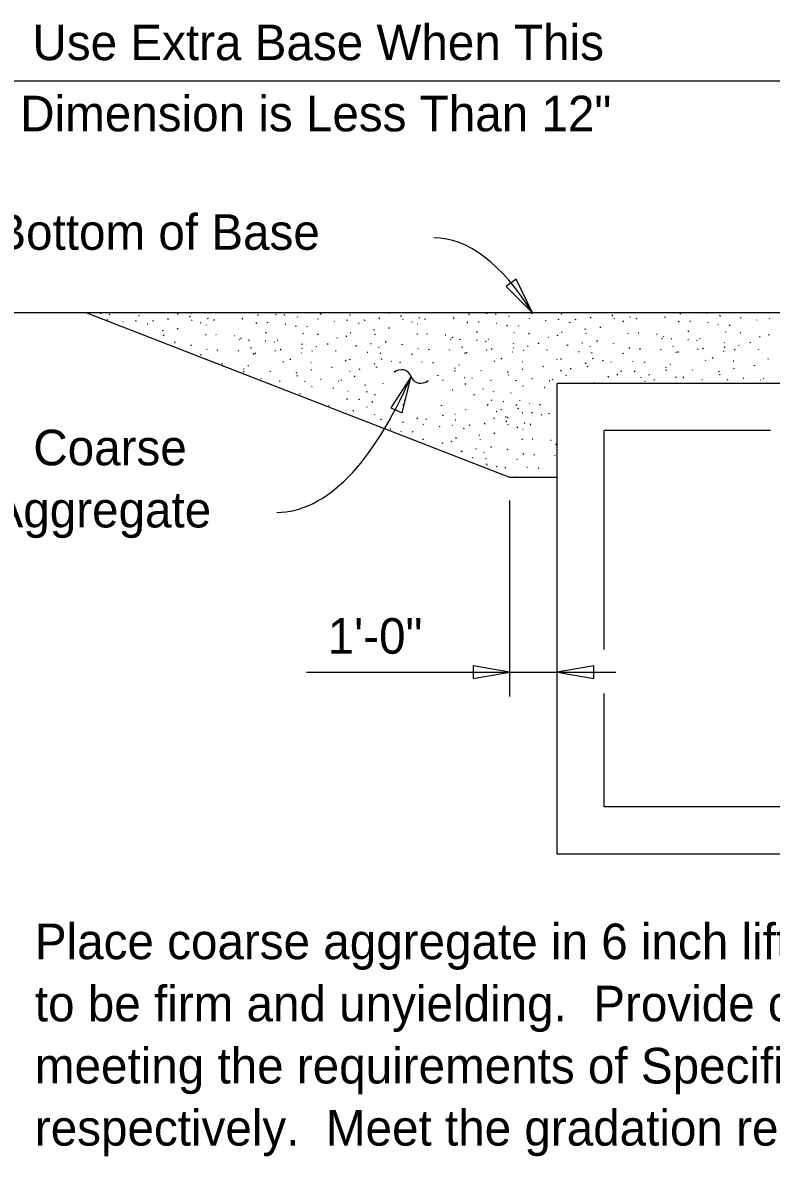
# Model space of a CAD drawing. Extents: x 1.4 to 54.1, y -0.5 to 22.6.
# Drawn here: x 23.827 to 27.007, y 6.775 to 11.592 of the extents above; entities that cross this region are included whole.
import ezdxf

# ---------------------------------------------------------------- set-up
doc = ezdxf.new("R2010")
doc.units = 0
for name, color, linetype in [('AdhocPoint_dp', 7, 'Continuous'), ('Border', 7, 'Continuous'), ('Leader', 7, 'Continuous'), ('PlotBorder_dp', 7, 'Continuous'), ('WallConc', 7, 'Continuous')]:
    doc.layers.add(name, color=color, linetype=linetype)

msp = doc.modelspace()

# ---------------------------------------------------------------- linework, layer by layer
at = {"layer": 'Border'}
for p, q in [((24.1612, 10.3536), (24.1592, 10.3569)), ((24.487, 10.3527), (24.4858, 10.3566)), ((24.5439, 10.3597), (24.5413, 10.3561)), ((25.0583, 10.3566), (25.0564, 10.3597)), ((25.3841, 10.3557), (25.3828, 10.3596)), ((25.4389, 10.3597), (25.4384, 10.359)), ((25.8005, 10.3537), (25.7985, 10.357)), ((25.9553, 10.3596), (25.9552, 10.3597)), ((25.9919, 10.3557), (25.9899, 10.3589)), ((26.2812, 10.3586), (26.2808, 10.3597)), ((26.6976, 10.3567), (26.6956, 10.3597)), ((26.7347, 10.3547), (26.7328, 10.358)), ((26.8889, 10.3586), (26.8883, 10.3597)), ((24.1873, 10.3275), (24.1854, 10.3307)), ((24.1978, 10.3497), (24.1958, 10.353)), ((24.2546, 10.3203), (24.2527, 10.3196)), ((24.3082, 10.3268), (24.3069, 10.3229)), ((24.3232, 10.3471), (24.32, 10.3477)), ((24.3592, 10.3111), (24.356, 10.3117)), ((24.3828, 10.3229), (24.3815, 10.3268)), ((24.4455, 10.3347), (24.4429, 10.3307)), ((24.5381, 10.3449), (24.5355, 10.341)), ((24.5469, 10.3263), (24.545, 10.3296)), ((24.5852, 10.3188), (24.5825, 10.3149)), ((24.6152, 10.3331), (24.6132, 10.3364)), ((24.6415, 10.3265), (24.6395, 10.3311)), ((24.761, 10.3363), (24.7584, 10.3325)), ((24.8198, 10.318), (24.8172, 10.3141)), ((24.8283, 10.3488), (24.8244, 10.3488)), ((24.8688, 10.316), (24.8668, 10.3193)), ((24.9034, 10.3507), (24.9014, 10.354)), ((24.9406, 10.3487), (24.9387, 10.352)), ((24.9446, 10.3096), (24.9426, 10.3128)), ((24.9949, 10.3429), (24.9929, 10.3396)), ((25.0844, 10.3305), (25.0824, 10.3337)), ((25.0948, 10.3527), (25.0929, 10.3559)), ((25.1517, 10.3233), (25.1497, 10.3226)), ((25.2053, 10.3298), (25.2039, 10.3259)), ((25.2203, 10.3501), (25.2171, 10.3507)), ((25.2563, 10.3141), (25.253, 10.3147)), ((25.2798, 10.3258), (25.2786, 10.3298)), ((25.3426, 10.3377), (25.34, 10.3337)), ((25.4352, 10.3479), (25.4326, 10.3439)), ((25.4439, 10.3293), (25.442, 10.3326)), ((25.4822, 10.3218), (25.4796, 10.3179)), ((25.5052, 10.3106), (25.5041, 10.3109)), ((25.5123, 10.3361), (25.5103, 10.3394)), ((25.5385, 10.3295), (25.5365, 10.3341)), ((25.6581, 10.3393), (25.6555, 10.3355)), ((25.7168, 10.321), (25.7142, 10.3171)), ((25.7253, 10.3518), (25.7214, 10.3517)), ((25.7658, 10.319), (25.7638, 10.3223)), ((25.8377, 10.3517), (25.8357, 10.355)), ((25.8416, 10.3125), (25.8396, 10.3158)), ((25.8919, 10.3459), (25.89, 10.3426)), ((25.9815, 10.3335), (25.9795, 10.3367)), ((26.0487, 10.3263), (26.0468, 10.3256)), ((26.1023, 10.3327), (26.101, 10.3289)), ((26.1173, 10.353), (26.1141, 10.3537)), ((26.1533, 10.317), (26.1501, 10.3177)), ((26.1769, 10.3288), (26.1757, 10.3328)), ((26.2396, 10.3406), (26.237, 10.3367)), ((26.3322, 10.3509), (26.3296, 10.3469)), ((26.341, 10.3323), (26.3391, 10.3356)), ((26.3793, 10.3248), (26.3766, 10.3208)), ((26.4023, 10.3136), (26.4011, 10.3139)), ((26.4093, 10.3391), (26.4074, 10.3424)), ((26.4356, 10.3325), (26.4336, 10.3371)), ((26.5551, 10.3423), (26.5525, 10.3384)), ((26.6139, 10.324), (26.6113, 10.3201)), ((26.6224, 10.3548), (26.6185, 10.3547)), ((26.6629, 10.322), (26.6609, 10.3253)), ((26.7387, 10.3155), (26.7367, 10.3188)), ((26.783, 10.3064), (26.7812, 10.3096)), ((26.789, 10.3488), (26.787, 10.3456)), ((26.8785, 10.3365), (26.8765, 10.3397)), ((26.9458, 10.3293), (26.9438, 10.3286)), ((26.9994, 10.3357), (26.998, 10.3319)), ((24.3239, 10.2732), (24.323, 10.2718)), ((24.424, 10.2817), (24.4227, 10.2857)), ((24.4279, 10.2622), (24.426, 10.2654)), ((24.4867, 10.2935), (24.4841, 10.2895)), ((24.6065, 10.2641), (24.6044, 10.2674)), ((24.6082, 10.3076), (24.607, 10.3079)), ((24.6493, 10.2665), (24.6473, 10.2671)), ((24.7276, 10.2612), (24.7251, 10.2613)), ((24.8609, 10.2769), (24.8583, 10.273)), ((24.9889, 10.3004), (24.987, 10.3036)), ((25.0197, 10.2696), (25.0178, 10.2729)), ((25.0197, 10.2696), (25.0178, 10.2729)), ((25.036, 10.3017), (25.0341, 10.2984)), ((25.0831, 10.2664), (25.0805, 10.2704)), ((25.2033, 10.2573), (25.202, 10.2612)), ((25.221, 10.2762), (25.2184, 10.2723)), ((25.321, 10.2847), (25.3197, 10.2887)), ((25.3249, 10.2651), (25.3231, 10.2684)), ((25.3838, 10.2965), (25.3812, 10.2925)), ((25.5035, 10.2671), (25.5015, 10.2704)), ((25.5463, 10.2694), (25.5444, 10.2701)), ((25.6247, 10.2642), (25.6221, 10.2642)), ((25.758, 10.2799), (25.7554, 10.2759)), ((25.886, 10.3034), (25.8841, 10.3066)), ((25.9167, 10.2726), (25.9148, 10.2759)), ((25.9167, 10.2726), (25.9148, 10.2759)), ((25.9331, 10.3047), (25.9312, 10.3014)), ((25.9802, 10.2694), (25.9776, 10.2733)), ((26.1004, 10.2602), (26.0991, 10.2641)), ((26.118, 10.2791), (26.1154, 10.2753)), ((26.2181, 10.2876), (26.2168, 10.2917)), ((26.222, 10.2681), (26.2201, 10.2714)), ((26.2808, 10.2995), (26.2782, 10.2955)), ((26.4006, 10.2701), (26.3985, 10.2734)), ((26.4434, 10.2724), (26.4414, 10.273)), ((26.5217, 10.2672), (26.5192, 10.2672)), ((26.655, 10.2829), (26.6524, 10.2789)), ((26.8138, 10.2756), (26.8119, 10.2789)), ((26.8138, 10.2756), (26.8119, 10.2789)), ((26.8301, 10.3077), (26.8282, 10.3044)), ((26.8772, 10.2724), (26.8746, 10.2763)), ((26.9975, 10.2632), (26.9962, 10.2671)), ((24.4743, 10.2354), (24.4717, 10.2327)), ((24.4736, 10.2308), (24.4717, 10.2314)), ((24.5436, 10.2196), (24.5423, 10.2235)), ((24.7499, 10.2429), (24.7479, 10.2461)), ((24.7565, 10.2494), (24.7551, 10.2534)), ((24.7897, 10.2409), (24.7878, 10.2442)), ((24.7976, 10.2083), (24.7962, 10.2123)), ((24.8603, 10.2383), (24.8576, 10.2383)), ((24.8982, 10.2331), (24.8962, 10.2363)), ((24.9106, 10.2416), (24.9087, 10.2448)), ((24.9106, 10.2416), (24.9087, 10.2448)), ((25.0158, 10.224), (25.0145, 10.2279)), ((25.0765, 10.2128), (25.0746, 10.2161)), ((25.1242, 10.2253), (25.1217, 10.2292)), ((25.1649, 10.25), (25.1628, 10.2533)), ((25.2445, 10.2161), (25.2432, 10.22)), ((25.2471, 10.2161), (25.2451, 10.2193)), ((25.3079, 10.2272), (25.3046, 10.2278)), ((25.3418, 10.2102), (25.34, 10.2134)), ((25.3714, 10.2384), (25.3687, 10.2357)), ((25.3707, 10.2337), (25.3688, 10.2344)), ((25.4407, 10.2226), (25.4394, 10.2265)), ((25.647, 10.2459), (25.6449, 10.2491)), ((25.6535, 10.2524), (25.6522, 10.2564)), ((25.6868, 10.2439), (25.6849, 10.2472)), ((25.6947, 10.2113), (25.6933, 10.2152)), ((25.7573, 10.2413), (25.7547, 10.2413)), ((25.7952, 10.2361), (25.7933, 10.2393)), ((25.8076, 10.2446), (25.8058, 10.2478)), ((25.8076, 10.2446), (25.8058, 10.2478)), ((25.9128, 10.227), (25.9115, 10.2309)), ((25.9735, 10.2158), (25.9716, 10.2191)), ((26.0213, 10.2283), (26.0187, 10.2322)), ((26.0619, 10.253), (26.0599, 10.2563)), ((26.1416, 10.2191), (26.1403, 10.223)), ((26.1442, 10.2191), (26.1422, 10.2223)), ((26.2049, 10.2302), (26.2017, 10.2308)), ((26.2389, 10.2132), (26.237, 10.2164)), ((26.2684, 10.2414), (26.2658, 10.2387)), ((26.2677, 10.2367), (26.2658, 10.2374)), ((26.3377, 10.2256), (26.3364, 10.2295)), ((26.544, 10.2488), (26.542, 10.2521)), ((26.5506, 10.2554), (26.5492, 10.2594)), ((26.5838, 10.2469), (26.5819, 10.2502)), ((26.5917, 10.2143), (26.5904, 10.2182)), ((26.6544, 10.2443), (26.6517, 10.2443)), ((26.6923, 10.239), (26.6903, 10.2423)), ((26.7047, 10.2476), (26.7028, 10.2508)), ((26.7047, 10.2476), (26.7028, 10.2508)), ((26.8099, 10.2299), (26.8086, 10.2338)), ((26.8105, 10.211), (26.8086, 10.2143)), ((26.8706, 10.2188), (26.8687, 10.2221)), ((26.9183, 10.2312), (26.9158, 10.2351)), ((26.959, 10.256), (26.9569, 10.2593)), ((24.5848, 10.1784), (24.5835, 10.1823)), ((24.6114, 10.2021), (24.6094, 10.2054)), ((24.6566, 10.1982), (24.6547, 10.2015)), ((24.7447, 10.1959), (24.7427, 10.1991)), ((24.7447, 10.1959), (24.7427, 10.1991)), ((24.81, 10.1828), (24.808, 10.186)), ((24.8165, 10.1894), (24.8139, 10.1854)), ((24.9014, 10.1972), (24.8988, 10.1972)), ((24.9237, 10.205), (24.9204, 10.2004)), ((24.9648, 10.1638), (24.9616, 10.1593)), ((25.0119, 10.1886), (25.01, 10.1893)), ((25.0164, 10.205), (25.0145, 10.2083)), ((25.0589, 10.1952), (25.0569, 10.1985)), ((25.0589, 10.1952), (25.0569, 10.1985)), ((25.1583, 10.1991), (25.1564, 10.1958)), ((25.2935, 10.1906), (25.2909, 10.1905)), ((25.3491, 10.186), (25.3458, 10.1866)), ((25.353, 10.1598), (25.351, 10.1644)), ((25.4818, 10.1814), (25.4805, 10.1853)), ((25.5084, 10.2051), (25.5065, 10.2084)), ((25.5537, 10.2012), (25.5517, 10.2044)), ((25.6417, 10.1988), (25.6397, 10.2021)), ((25.6417, 10.1988), (25.6397, 10.2021)), ((25.707, 10.1858), (25.7051, 10.189)), ((25.7136, 10.1923), (25.711, 10.1884)), ((25.7985, 10.2001), (25.7959, 10.2001)), ((25.8207, 10.208), (25.8175, 10.2034)), ((25.8619, 10.1668), (25.8586, 10.1622)), ((25.9089, 10.1916), (25.907, 10.1923)), ((25.9135, 10.208), (25.9115, 10.2113)), ((25.9559, 10.1982), (25.954, 10.2014)), ((25.9559, 10.1982), (25.954, 10.2014)), ((26.0553, 10.202), (26.0534, 10.1988)), ((26.1148, 10.1609), (26.1142, 10.1654)), ((26.1906, 10.1936), (26.188, 10.1935)), ((26.2461, 10.189), (26.2429, 10.1896)), ((26.2501, 10.1628), (26.2481, 10.1674)), ((26.3789, 10.1844), (26.3776, 10.1883)), ((26.4055, 10.2081), (26.4035, 10.2114)), ((26.4507, 10.2042), (26.4488, 10.2074)), ((26.5388, 10.2018), (26.5368, 10.2051)), ((26.5388, 10.2018), (26.5368, 10.2051)), ((26.6041, 10.1888), (26.6021, 10.192)), ((26.6107, 10.1953), (26.6081, 10.1914)), ((26.6955, 10.2031), (26.6929, 10.2031)), ((26.7178, 10.2109), (26.7145, 10.2064)), ((26.7589, 10.1698), (26.7557, 10.1652)), ((26.806, 10.1946), (26.8041, 10.1953)), ((26.853, 10.2012), (26.851, 10.2044)), ((26.853, 10.2012), (26.851, 10.2044)), ((26.9524, 10.205), (26.9505, 10.2018)), ((26.9935, 10.1638), (26.9916, 10.1607)), ((24.6753, 10.1411), (24.674, 10.145)), ((24.7682, 10.1201), (24.7649, 10.1207)), ((24.7858, 10.1325), (24.7839, 10.1357)), ((24.9348, 10.1495), (24.9328, 10.1528)), ((25.053, 10.1475), (25.0511, 10.1482)), ((25.0544, 10.1161), (25.0518, 10.1187)), ((25.1419, 10.1304), (25.1394, 10.1265)), ((25.1994, 10.1579), (25.1975, 10.1547)), ((25.2177, 10.1579), (25.2171, 10.1625)), ((25.2589, 10.1167), (25.2583, 10.1213)), ((25.3229, 10.1403), (25.3209, 10.1435)), ((25.3309, 10.1259), (25.3295, 10.1298)), ((25.3956, 10.1513), (25.3936, 10.1546)), ((25.4302, 10.1481), (25.4276, 10.1467)), ((25.4316, 10.1495), (25.4308, 10.149)), ((25.5243, 10.1481), (25.5223, 10.1513)), ((25.5724, 10.1441), (25.5711, 10.148)), ((25.6652, 10.123), (25.662, 10.1237)), ((25.6829, 10.1355), (25.6809, 10.1387)), ((25.8319, 10.1525), (25.8299, 10.1557)), ((25.9501, 10.1505), (25.9481, 10.1512)), ((25.9515, 10.1191), (25.9488, 10.1217)), ((26.039, 10.1334), (26.0364, 10.1295)), ((26.0965, 10.1609), (26.0946, 10.1577)), ((26.1559, 10.1197), (26.1553, 10.1243)), ((26.22, 10.1433), (26.218, 10.1465)), ((26.228, 10.1288), (26.2265, 10.1327)), ((26.2926, 10.1542), (26.2906, 10.1576)), ((26.3272, 10.1511), (26.3246, 10.1497)), ((26.3286, 10.1524), (26.3278, 10.152)), ((26.4214, 10.1511), (26.4194, 10.1543)), ((26.4694, 10.1471), (26.4681, 10.151)), ((26.5623, 10.126), (26.559, 10.1267)), ((26.5616, 10.1136), (26.5596, 10.1169)), ((26.5799, 10.1385), (26.578, 10.1417)), ((26.6734, 10.1143), (26.6714, 10.1175)), ((26.7289, 10.1554), (26.7269, 10.1587)), ((26.8471, 10.1535), (26.8452, 10.1541)), ((26.8485, 10.1221), (26.8459, 10.1247)), ((26.936, 10.1364), (26.9335, 10.1325)), ((24.7675, 10.1076), (24.7655, 10.1109)), ((24.8407, 10.0776), (24.8387, 10.0809)), ((24.8793, 10.1083), (24.8772, 10.1116)), ((24.9204, 10.0672), (24.9184, 10.0704)), ((24.9916, 10.1017), (24.9903, 10.1057)), ((24.9949, 10.0894), (24.9929, 10.0926)), ((25.0276, 10.0658), (25.0263, 10.0697)), ((25.0956, 10.0749), (25.093, 10.0775)), ((25.1687, 10.0671), (25.1668, 10.0678)), ((25.1811, 10.0717), (25.1792, 10.0749)), ((25.2184, 10.1089), (25.2164, 10.1122)), ((25.2393, 10.088), (25.2373, 10.0912)), ((25.5922, 10.0906), (25.5908, 10.0944)), ((25.6138, 10.0716), (25.6105, 10.0723)), ((25.6646, 10.1106), (25.6626, 10.1139)), ((25.7064, 10.0819), (25.7031, 10.0825)), ((25.7378, 10.0806), (25.7358, 10.0838)), ((25.7763, 10.1113), (25.7743, 10.1146)), ((25.8175, 10.0702), (25.8155, 10.0734)), ((25.8887, 10.1047), (25.8873, 10.1087)), ((25.892, 10.0924), (25.89, 10.0956)), ((25.9246, 10.0688), (25.9233, 10.0727)), ((25.9926, 10.0779), (25.99, 10.0805)), ((26.0658, 10.0701), (26.0639, 10.0707)), ((26.0782, 10.0746), (26.0762, 10.0779)), ((26.1154, 10.1119), (26.1135, 10.1151)), ((26.1364, 10.091), (26.1344, 10.0942)), ((26.3155, 10.0896), (26.3128, 10.0856)), ((26.3547, 10.0948), (26.3526, 10.0981)), ((26.3684, 10.1099), (26.3658, 10.1086)), ((26.3698, 10.1113), (26.3689, 10.1109)), ((26.4279, 10.1093), (26.426, 10.1126)), ((26.454, 10.0831), (26.4521, 10.0864)), ((26.4717, 10.0655), (26.4697, 10.0688)), ((26.4892, 10.0936), (26.4879, 10.0974)), ((26.5109, 10.0746), (26.5076, 10.0753)), ((26.6034, 10.0849), (26.6002, 10.0855)), ((26.6348, 10.0836), (26.6328, 10.0868)), ((26.7145, 10.0731), (26.7125, 10.0764)), ((26.7857, 10.1077), (26.7844, 10.1117)), ((26.789, 10.0954), (26.787, 10.0986)), ((26.8217, 10.0717), (26.8204, 10.0756)), ((26.8897, 10.0809), (26.8871, 10.0835)), ((26.9628, 10.073), (26.9609, 10.0737)), ((26.9752, 10.0776), (26.9733, 10.0809)), ((25.0557, 10.0468), (25.0537, 10.0436)), ((25.1471, 10.0377), (25.1452, 10.0409)), ((25.2098, 10.026), (25.2079, 10.0266)), ((25.2832, 10.0494), (25.2813, 10.054)), ((25.2903, 10.0213), (25.2884, 10.0245)), ((25.3583, 10.0566), (25.3564, 10.0598)), ((25.6549, 10.0305), (25.6517, 10.0311)), ((25.7083, 10.0591), (25.7057, 10.0551)), ((25.7848, 10.0336), (25.7828, 10.0368)), ((25.8286, 10.0224), (25.8267, 10.0257)), ((25.9024, 10.0165), (25.9005, 10.0198)), ((25.9528, 10.0498), (25.9508, 10.0466)), ((26.0442, 10.0406), (26.0422, 10.0439)), ((26.2552, 10.0597), (26.2534, 10.0628)), ((26.6053, 10.062), (26.6038, 10.0597)), ((25.0054, 10.0136), (25.0035, 10.0168)), ((25.2048, 9.9957), (25.2028, 9.9912)), ((25.2576, 9.9887), (25.2558, 9.9919)), ((25.2576, 9.9887), (25.2558, 9.9919)), ((25.3133, 9.9827), (25.3106, 9.9787)), ((25.3243, 10.0082), (25.3224, 10.0128)), ((25.4445, 9.9677), (25.4432, 9.9716)), ((25.4511, 9.9873), (25.4471, 9.9873)), ((25.7466, 10.0088), (25.7447, 10.0121)), ((25.8194, 9.9871), (25.8175, 9.9904)), ((25.8705, 9.9806), (25.8685, 9.9839)), ((25.9404, 9.9852), (25.9384, 9.9884)), ((25.9802, 9.9741), (25.9783, 9.9734)), ((25.1288, 9.9645), (25.127, 9.9677)), ((25.2342, 9.9429), (25.2302, 9.9429)), ((25.2904, 9.9573), (25.2884, 9.9606)), ((25.2904, 9.9573), (25.2884, 9.9606)), ((25.2904, 9.9573), (25.2884, 9.9606)), ((25.323, 9.9246), (25.3211, 9.9279)), ((25.6059, 9.967), (25.6046, 9.9632)), ((25.6111, 9.924), (25.6098, 9.92)), ((25.6648, 9.9279), (25.6629, 9.9286)), ((25.7112, 9.9455), (25.7092, 9.9488)), ((25.8038, 9.9699), (25.7998, 9.966)), ((25.841, 9.942), (25.8384, 9.9381)), ((25.8606, 9.9459), (25.8587, 9.9492)), ((25.9253, 9.9701), (25.9214, 9.9662)), ((25.9332, 9.9505), (25.9312, 9.9538)), ((25.9508, 9.9328), (25.9488, 9.9362)), ((25.9508, 9.9328), (25.9488, 9.9362)), ((25.992, 9.9336), (25.99, 9.9367)), ((26.0259, 9.9675), (26.024, 9.9707)), ((26.0319, 9.9237), (26.0306, 9.9276)), ((26.0639, 9.9334), (26.0614, 9.9295)), ((25.2753, 9.9018), (25.2745, 9.9018)), ((25.3505, 9.9037), (25.3484, 9.9069)), ((25.3876, 9.9017), (25.3857, 9.905)), ((25.4419, 9.8958), (25.44, 9.8926)), ((25.5053, 9.9096), (25.5033, 9.9128)), ((25.5314, 9.8835), (25.5295, 9.8867)), ((25.5418, 9.9056), (25.5399, 9.9089)), ((25.5987, 9.8763), (25.5968, 9.8756)), ((25.6523, 9.8827), (25.651, 9.8789)), ((25.6673, 9.903), (25.6641, 9.9037)), ((25.7269, 9.8788), (25.7256, 9.8828)), ((25.7896, 9.8906), (25.787, 9.8867)), ((25.8311, 9.9086), (25.8299, 9.9126)), ((25.8802, 9.9159), (25.8783, 9.9191)), ((25.8822, 9.9009), (25.8796, 9.8969)), ((25.8881, 9.9159), (25.8854, 9.912)), ((25.891, 9.8823), (25.8891, 9.8855)), ((25.9293, 9.8747), (25.9266, 9.8708)), ((25.9593, 9.889), (25.9573, 9.8924)), ((25.9856, 9.8825), (25.9836, 9.8871)), ((25.3916, 9.8625), (25.3896, 9.8658)), ((25.4359, 9.8534), (25.4341, 9.8566)), ((25.4831, 9.8547), (25.4811, 9.8514)), ((25.668, 9.8291), (25.6654, 9.8253)), ((25.7033, 9.867), (25.7, 9.8677)), ((25.7681, 9.8376), (25.7668, 9.8416)), ((25.8308, 9.8494), (25.8282, 9.8455)), ((25.9522, 9.8635), (25.9511, 9.8639)), ((25.5301, 9.8194), (25.5275, 9.8233)), ((25.6119, 9.803), (25.6099, 9.8063)), ((25.6504, 9.8102), (25.6491, 9.8141)), ((25.7549, 9.7801), (25.7516, 9.7808)), ((25.772, 9.8181), (25.7701, 9.8213)), ((25.8184, 9.7913), (25.8157, 9.7887)), ((25.8177, 9.7867), (25.8158, 9.7874)), ((25.8877, 9.7756), (25.8864, 9.7795)), ((25.9505, 9.8201), (25.9485, 9.8234)), ((25.9934, 9.8224), (25.9914, 9.823)), ((26.0717, 9.8171), (26.0692, 9.8172)), ((26.094, 9.7988), (26.092, 9.8021)), ((25.6916, 9.769), (25.6903, 9.7729)), ((25.6942, 9.769), (25.6922, 9.7723)), ((25.7405, 9.7436), (25.7379, 9.7435)), ((25.7889, 9.7632), (25.787, 9.7664)), ((25.7961, 9.7389), (25.7929, 9.7396)), ((25.9289, 9.7344), (25.9276, 9.7383)), ((25.9555, 9.758), (25.9535, 9.7614)), ((26.0007, 9.7542), (25.9987, 9.7574)), ((26.0887, 9.7518), (26.0868, 9.755)), ((26.0887, 9.7518), (26.0868, 9.755)), ((25.8001, 9.7128), (25.7981, 9.7174)), ((25.8426, 9.7042), (25.8406, 9.7076)), ((25.8772, 9.701), (25.8746, 9.6997)), ((25.8786, 9.7024), (25.8778, 9.702)), ((25.9714, 9.7011), (25.9694, 9.7043)), ((26.0194, 9.697), (26.0181, 9.701)), ((25.9184, 9.6599), (25.9181, 9.6597)), ((25.9198, 9.6612), (25.9189, 9.6608)), ((25.9776, 9.6597), (25.9759, 9.6625))]:
    msp.add_line(p, q, dxfattribs=at)
at = {"layer": 'Leader'}
for centre, major_axis, ratio, start_param, end_param in [((25.5525, 6.9571), (-0.0208, -3.7212), 0.280395, 2.726334, 3.141593), ((24.8823, 12.2769), (-0.0248, 2.7656), 0.341299, 3.141593, 3.796631)]:
    msp.add_ellipse(centre, major_axis=major_axis, ratio=ratio, start_param=start_param, end_param=end_param, dxfattribs=at)
at = {"layer": 'PlotBorder_dp'}
for p, q in [((23.6639, 11.3451), (27.0785, 11.3451)), ((25.8968, 8.729), (25.8968, 9.5616)), ((25.0324, 8.8327), (25.8968, 8.8327)), ((25.8968, 8.8327), (26.0968, 8.8327)), ((26.0968, 8.8327), (26.3468, 8.8327))]:
    msp.add_line(p, q, dxfattribs=at)
for points in [[(25.9925, 10.3597), (25.9238, 10.5025), (25.8806, 10.4719)], [(25.4769, 10.0888), (25.3905, 9.956), (25.4391, 9.935)], [(25.8968, 8.8327), (25.7406, 8.8592), (25.7406, 8.8063)], [(26.0968, 8.8327), (26.253, 8.8063), (26.253, 8.8592)]]:
    msp.add_lwpolyline(points, close=True, dxfattribs=at)
for centre, start, end in [((25.4351, 10.073), 20.737, 132.4642), ((25.5187, 10.1046), 200.737, 312.4642)]:
    msp.add_arc(centre, 0.0447, start, end, dxfattribs=at)
at = {"layer": 'WallConc'}
for p, q in [((31.2968, 10.3597), (23.6968, 10.3597)), ((25.8968, 9.6597), (24.0968, 10.3597)), ((28.8968, 10.0597), (26.0968, 10.0597)), ((26.0968, 8.0597), (26.0968, 10.0597)), ((26.2968, 8.9291), (26.2968, 9.8597)), ((27.0029, 9.8597), (26.2968, 9.8597)), ((26.0968, 9.6597), (25.8968, 9.6597)), ((26.2968, 8.2597), (26.2968, 8.7419)), ((28.6968, 8.2597), (26.2968, 8.2597)), ((28.8968, 8.0597), (26.0968, 8.0597))]:
    msp.add_line(p, q, dxfattribs=at)

# ---------------------------------------------------------------- texts
at = {"layer": 'AdhocPoint_dp'}
for s, p in [('Use Extra Base When This', (23.8689, 11.433)), ('Dimension is Less Than 12"', (23.8168, 11.1306)), ('Bottom of Base', (23.707, 10.6272)), ('Coarse', (23.8726, 9.7114)), ('Aggregate', (23.6951, 9.4474)), ('1\'-0"', (25.1225, 8.9109)), ('Place coarse aggregate in 6 inch lifts and compact sufficiently as', (23.8791, 7.613)), ('to be firm and unyielding.  Provide coarse aggregate gravel or stone', (23.8791, 7.349)), ('meeting the requirements of Specification Section 901-2 or 901-3', (23.8791, 7.085)), ('respectively.  Meet the gradation requirements of Specification', (23.8791, 6.821))]:
    msp.add_text(s, height=0.1512, dxfattribs=at).set_placement(p)

doc.saveas('drawing.dxf')
